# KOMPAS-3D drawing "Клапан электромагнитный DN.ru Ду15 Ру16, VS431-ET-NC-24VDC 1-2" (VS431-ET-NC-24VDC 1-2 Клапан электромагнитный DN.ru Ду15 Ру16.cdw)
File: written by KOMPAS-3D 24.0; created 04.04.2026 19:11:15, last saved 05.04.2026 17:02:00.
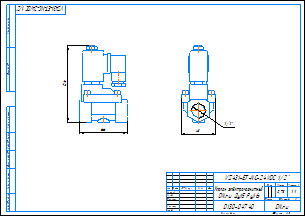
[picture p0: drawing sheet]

Document properties: c3d_UniqueCompID: ef56311e-7521-43dc-8291-0e6108b3d81d; Обозначение: VS400-ET-NC-220VAC 1-2; Наименование: Клапан электромагнитный DN.ru Ду15 Ру16; Автор: artio; Класс точности: c; Знак неуказанной шероховатости: Шероховатость не задана; Рассекать на разрезах: Да; c3d_UniqueCompID: ef56311e-7521-43dc-8291-0e6108b3d81d; Обозначение: VS400-ET-NC-220VAC 3-8; Наименование: Клапан электромагнитный DN.ru Ду10 Ру16; Автор: artio; Класс точности: c; Знак неуказанной шероховатости: Шероховатость не задана; Рассекать на разрезах: Да; Автор: artio; Форматы листов документа: A3; Полное имя файла: VS431-ET-NC-24VDC 1-2 Клапан электромагнитный DN.ru Ду15 Ру16.m3d; Масса: 0.732; Наименование: Клапан электромагнитный DN.ru Ду15 Ру16; Количество листов документа: 1; Примечание: D130-04740

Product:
- Body: Тело 1  | qty 1
    Масса: 1.030062
- Part/product: Клапан электромагнитный DN.ru Ду15 Ру16  | designation VS431-ET-NC-24VDC 1-2
    Масса: 0.732
    Раздел спецификации: Прочие изделия
    Примечание: D130-04740
    additional columns: ef56311e-7521-43dc-8291-0e6108b3d81d; VS400-ET-NC-220VAC 1-2; artio; c; Шероховатость не задана; Да

Views: Вид 1, Спереди, Проекционный вид 2
Referenced files in C:\Users\artio\OneDrive\Рабочий стол\Клапан электромагнитный DN.ru\VS400-ET-NC\VS400-ET-NC-24VDC\: VS400-ET-NC-24VDC 3-8 Клапан электромагнитный DN.ru Ду10 Ру16.m3d
Referenced files in C:\Users\artio\OneDrive\Рабочий стол\Клапан электромагнитный DN.ru\VS431\VS431-ET-NC\VS431-ET-NC-24VDC\Ду15\: VS431-ET-NC-24VDC 1-2 Клапан электромагнитный DN.ru Ду15 Ру16.m3d
Referenced files in C:\Users\artio\OneDrive\Рабочий стол\Клапан электромагнитный DN.ru\VS400-ET-NC\: VS400-ET-NC-24VDC 3-8 Клапан электромагнитный DN.ru Ду10 Ру16.cdw
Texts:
  VS431-ET-NC-24VDC 1-2
  Клапан электромагнитный
  DN.ru Ду15 Ру16
  VS431-ET-NC-24VDC 1/2"
  VS431-ET-NC-24VDC 1/2"-
  Клапан электромагнитный DN.ru Ду15 Ру16
  VS431-ET-NC-24VDC 1-2 Клапан электромагнитный DN.ru Ду15 Ру16
Dimensions and other numbers on the sheet: 0; 3; 2; 4; 48; 1/2"; 66; 106; 1:1; 1; 0,73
